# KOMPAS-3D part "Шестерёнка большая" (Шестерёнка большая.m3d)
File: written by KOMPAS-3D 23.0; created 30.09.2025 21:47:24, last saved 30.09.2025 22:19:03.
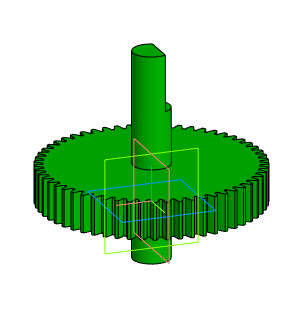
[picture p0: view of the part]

Document properties: Автор: Inspektor_Kot; Полное имя файла: C:\Users\Lost\Desktop\Варианты\Вариант 7\Вариант 7\Шестерёнка большая.m3d

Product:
- Part/product: Шестерёнка большая
    Масса: 1.799532

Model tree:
1. Операция без истории:1
2. Эскиз:1  (with: Операция без истории:1)
3. Элемент выдавливания:1
     Расстояние 1 = 30; Расстояние 2 = 50
4. Эскиз:2  (with: Элемент выдавливания:1)
5. Элемент выдавливания:2
     Расстояние 1 = 30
